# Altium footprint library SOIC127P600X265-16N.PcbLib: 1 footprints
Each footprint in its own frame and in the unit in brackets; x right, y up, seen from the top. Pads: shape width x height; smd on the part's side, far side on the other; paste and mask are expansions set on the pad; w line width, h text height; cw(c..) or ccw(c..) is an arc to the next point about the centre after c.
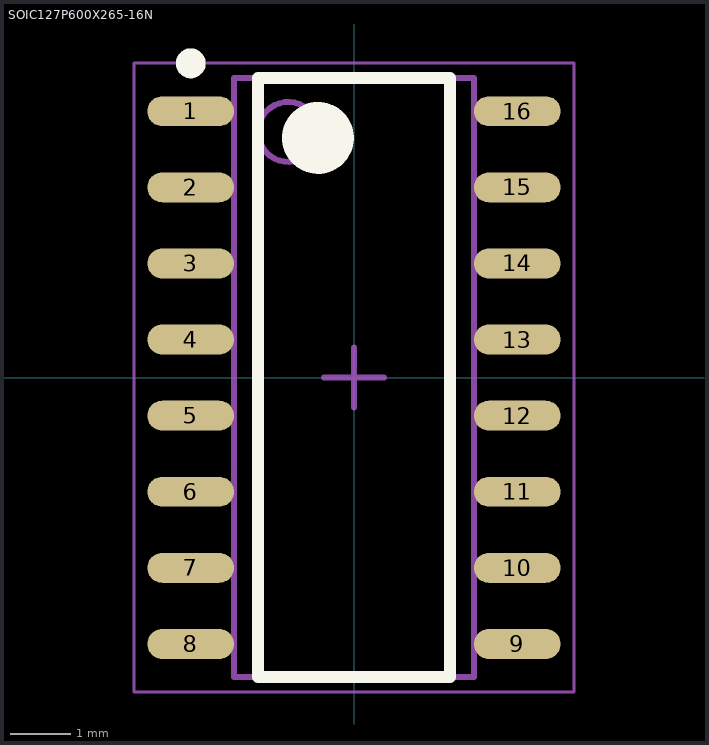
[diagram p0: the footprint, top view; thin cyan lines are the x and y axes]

## SOIC127P600X265-16N [mm] "SOIC, 16-Leads, Body 10.00x4.00mm, Pitch 1.27mm, IPC Medium Density"
height 2.65
pads (16):
  oval 1.45x0.5 smd: 1(-2.725,4.445) 2(-2.725,3.175) 3(-2.725,1.905) 4(-2.725,0.635) 5(-2.725,-0.635) 6(-2.725,-1.905) 7(-2.725,-3.175) 8(-2.725,-4.445) 9(2.725,-4.445) 10(2.725,-3.175) 11(2.725,-1.905) 12(2.725,-0.635) 13(2.725,0.635) 14(2.725,1.905) 15(2.725,3.175) 16(2.725,4.445)
Top Overlay:
  circle w0.6: c-0.6,4 r0.3
  circle w0.25: c-2.725,5.245 r0.125
  lines w0.2: -1.6,-5 1.6,-5 1.6,5 -1.6,5 -1.6,-5
Mechanical 13:
  circle w0.1: c-1.1,4.1 r0.5
  lines w0.1: -2,-5 2,-5 2,5 -2,5 -2,-5
Mechanical 15:
  lines w0.05: -3.675,-5.25 3.675,-5.25 3.675,5.25 -3.675,5.25 -3.675,-5.25
  lines w0.1: -0.5,0 0.5,0 ; 0,-0.5 0,0.5
3D body: height 2.65, standoff 0.1, extent -2,-5 2,5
